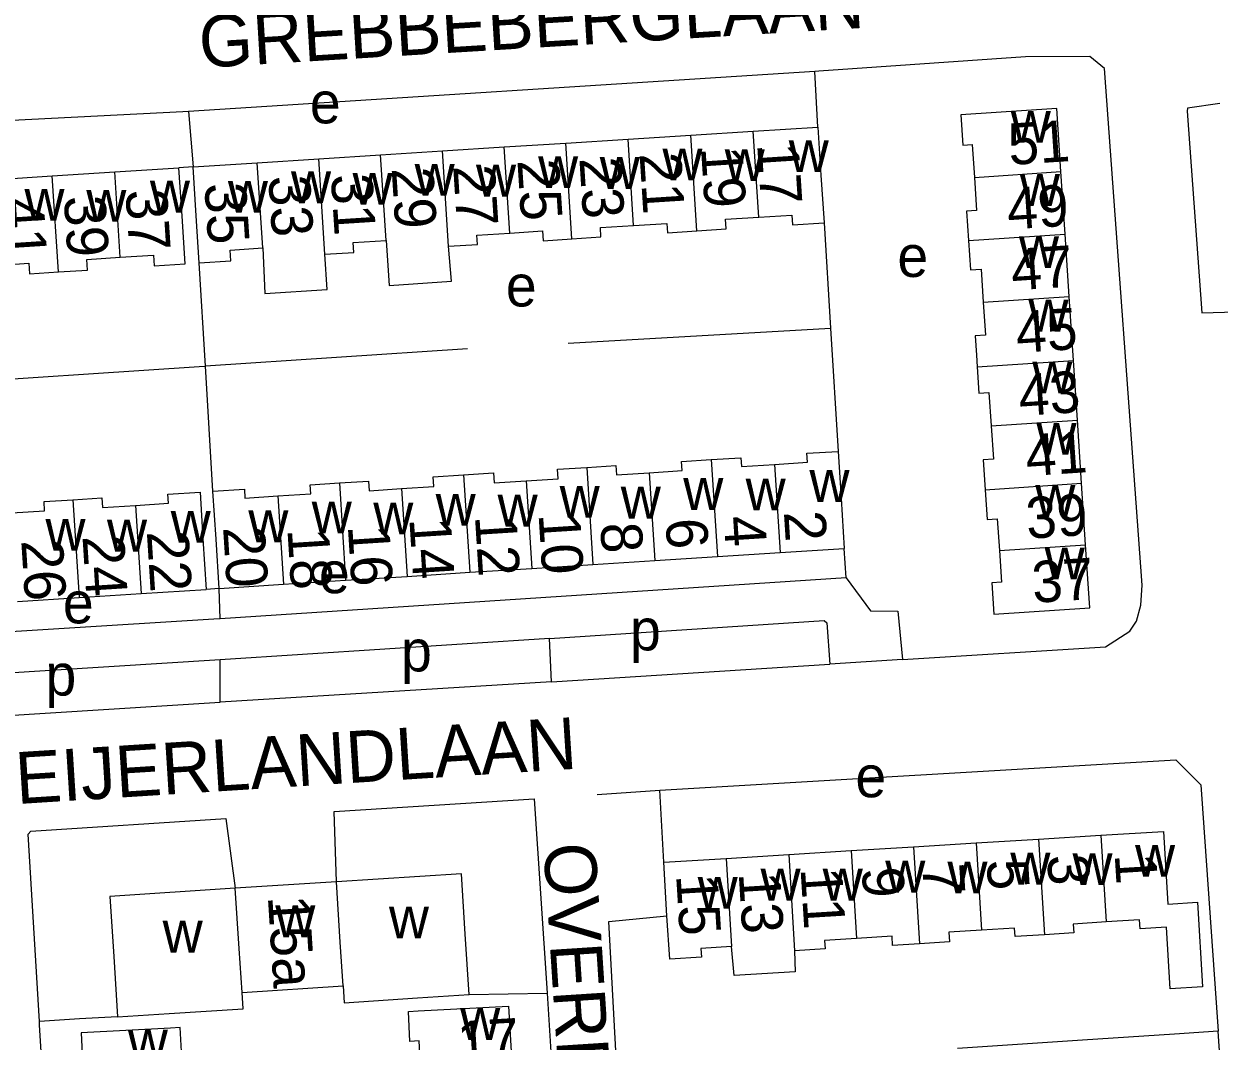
# Model space of a CAD drawing. Extents: x 159675 to 162108, y 386471 to 388472.
# Drawn here: x 160562.1 to 160677.4, y 387933.8 to 388032 of the extents above; entities that cross this region are included whole.
import ezdxf

# ---------------------------------------------------------------- set-up
doc = ezdxf.new("R2010")
doc.units = 0
for name, color, linetype in [('BLT_Basislijn', 7, 'Continuous'), ('BLT_Bebouwing', 7, 'Continuous'), ('BLT_Centroide', 7, 'Continuous'), ('BLT_Huisnummer', 7, 'Continuous'), ('BLT_Huisnummer_ tussenligend', 7, 'Continuous'), ('BLT_Onderverdeling_panden', 7, 'Continuous'), ('BLT_Straatnaam', 7, 'Continuous')]:
    doc.layers.add(name, color=color, linetype=linetype)

msp = doc.modelspace()

# ---------------------------------------------------------------- linework, layer by layer
at = {"layer": 'BLT_Basislijn'}
for p, q in [((160638.41, 388027.39), (160577.95, 388023.53)), ((160638.69, 388022.02), (160638.41, 388027.39)), ((160577.95, 388023.53), (160578.39, 388018.18)), ((160578.39, 388018.18), (160577.02, 388018.09)), ((160639.29, 388012.78), (160639.91, 388002.61)), ((160579.58, 387998.95), (160578.98, 388008.91)), ((160614.58, 388001.16), (160639.91, 388002.61)), ((160639.91, 388002.61), (160640.64, 387990.71)), ((160604.87, 388000.62), (160579.58, 387998.95)), ((160580.31, 387986.86), (160579.58, 387998.95)), ((160641.43, 387978.5), (160641.24, 387981.34)), ((160641.43, 387978.5), (160580.99, 387974.55)), ((160580.91, 387977.48), (160579.66, 387977.38)), ((160580.99, 387974.55), (160580.91, 387977.48)), ((160612.8, 387972.64), (160581, 387970.59)), ((160612.98, 387968.44), (160612.8, 387972.64)), ((160581, 387970.59), (160550.17, 387968.63)), ((160581, 387966.49), (160581, 387970.59)), ((160646.87, 387970.6), (160639.85, 387970.15)), ((160612.98, 387968.44), (160639.85, 387970.15)), ((160612.98, 387968.44), (160581, 387966.49)), ((160550.44, 387964.58), (160581, 387966.49)), ((160617.39, 387957.58), (160623.43, 387957.98)), ((160623.81, 387951.04), (160623.43, 387957.98)), ((160605.04, 387938.25), (160612.57, 387938.39)), ((160612.57, 387938.39), (160616.09, 387883.15))]:
    msp.add_line(p, q, dxfattribs=at)
for points in [[(160646.87, 387970.6), (160666.45, 387971.85), (160668.81, 387973.35), (160669.44, 387974.3), (160669.88, 387975.85), (160670, 387977.8), (160666.36, 388027.67), (160664.93, 388028.84), (160658.72, 388028.79), (160638.8, 388027.41), (160638.41, 388027.39)], [(160577.95, 388023.53), (160577.4, 388023.5), (160516.53, 388020.39)], [(160677.49, 388024.29), (160674.38, 388023.86), (160674.35, 388023.57), (160675.75, 388004.1), (160681.26, 388004.23)], [(160552.73, 387997.17), (160578.99, 387998.91), (160579.58, 387998.95)], [(160641.43, 387978.5), (160643.76, 387975.32), (160646.4, 387975.29), (160646.87, 387970.6)], [(160580.99, 387974.55), (160580.4, 387974.51), (160519.48, 387970.7)], [(160612.8, 387972.64), (160639.31, 387974.37), (160639.56, 387974.15), (160639.85, 387970.15)], [(160623.43, 387957.98), (160673.26, 387960.91), (160675.65, 387958.52), (160677.32, 387934.73)], [(160592.22, 387949.14), (160592.02, 387955.94), (160611.31, 387957.17), (160612.57, 387938.39)], [(160563.56, 387935.67), (160562.48, 387953.76), (160562.74, 387954.03), (160581.55, 387955.26), (160582.46, 387948.52)], [(160626.68, 387931.37), (160619.29, 387931.07), (160618.52, 387945.33), (160624.13, 387945.86)], [(160571.1, 387936.12), (160567.42, 387935.91), (160563.56, 387935.67)], [(160567.08, 387879.85), (160563.58, 387935.29), (160563.56, 387935.67)], [(160677.32, 387934.73), (160673.1, 387934.42), (160664.24, 387933.86), (160652.18, 387933.04)], [(160673.63, 387866.07), (160679.58, 387866.28), (160681.79, 387868.46), (160677.32, 387934.73)]]:
    msp.add_lwpolyline(points, dxfattribs=at)
at = {"layer": 'BLT_Bebouwing'}
for p, q in [((160620.37, 388020.86), (160626.42, 388021.24)), ((160626.42, 388021.24), (160632.46, 388021.62)), ((160632.46, 388021.62), (160638.69, 388022.02)), ((160602.46, 388019.72), (160608.41, 388020.1)), ((160608.41, 388020.1), (160614.37, 388020.47)), ((160614.37, 388020.47), (160620.37, 388020.86)), ((160584.58, 388018.58), (160590.53, 388018.96)), ((160590.53, 388018.96), (160596.49, 388019.34)), ((160596.49, 388019.34), (160602.46, 388019.72)), ((160564.8, 388017.31), (160570.82, 388017.69)), ((160570.82, 388017.69), (160577.02, 388018.09)), ((160578.39, 388018.18), (160584.58, 388018.58)), ((160662.56, 388011.69), (160662.16, 388017.72)), ((160558.83, 388016.92), (160564.8, 388017.31)), ((160662.96, 388005.67), (160662.56, 388011.69)), ((160663.37, 387999.49), (160662.96, 388005.67)), ((160654, 388000), (160654.07, 387998.87)), ((160663.75, 387993.72), (160663.37, 387999.49)), ((160664.15, 387987.63), (160663.75, 387993.72)), ((160664.54, 387981.69), (160664.15, 387987.63)), ((160629, 387980.55), (160635.05, 387980.94)), ((160635.05, 387980.94), (160641.24, 387981.34)), ((160664.95, 387975.61), (160664.54, 387981.69)), ((160611.08, 387979.41), (160616.98, 387979.79)), ((160616.98, 387979.79), (160622.96, 387980.17)), ((160622.96, 387980.17), (160629, 387980.55)), ((160593.11, 387978.26), (160599.05, 387978.64)), ((160599.05, 387978.64), (160605.09, 387979.03)), ((160605.09, 387979.03), (160611.08, 387979.41)), ((160573.37, 387976.98), (160579.66, 387977.38)), ((160580.91, 387977.48), (160587.12, 387977.88)), ((160587.12, 387977.88), (160593.11, 387978.26)), ((160561.44, 387976.21), (160567.39, 387976.59)), ((160567.39, 387976.59), (160573.37, 387976.98)), ((160653.96, 387952.9), (160659.99, 387953.27)), ((160659.99, 387953.27), (160666.02, 387953.65)), ((160629.85, 387951.41), (160635.88, 387951.78)), ((160635.88, 387951.78), (160641.9, 387952.16)), ((160641.9, 387952.16), (160647.93, 387952.53)), ((160647.93, 387952.53), (160653.96, 387952.9)), ((160623.81, 387951.04), (160629.85, 387951.41)), ((160624.13, 387945.86), (160623.81, 387951.04)), ((160592.22, 387949.14), (160582.46, 387948.52)), ((160605.04, 387938.25), (160604.66, 387944.1)), ((160570.73, 387941.93), (160571.1, 387936.12)), ((160583.11, 387938.47), (160592.86, 387939.09))]:
    msp.add_line(p, q, dxfattribs=at)
for points in [[(160662.16, 388017.72), (160661.75, 388023.83), (160652.48, 388023.21), (160652.67, 388020.29), (160653.6, 388020.35), (160653.81, 388017.16)], [(160638.69, 388022.02), (160638.99, 388017.38), (160639.29, 388012.78)], [(160571.35, 388009.45), (160574.56, 388009.65), (160574.62, 388008.62), (160577.62, 388008.81), (160577.32, 388013.42), (160577.02, 388018.09)], [(160578.98, 388008.91), (160578.69, 388013.46), (160578.39, 388018.18)], [(160653.81, 388017.16), (160654.02, 388013.98), (160653.05, 388013.91), (160653.24, 388011.08)], [(160627.01, 388012), (160629.84, 388012.18), (160629.78, 388013.12), (160632.99, 388013.32)], [(160632.99, 388013.32), (160636.19, 388013.53), (160636.26, 388012.59), (160639.29, 388012.78)], [(160603.05, 388010.51), (160605.85, 388010.69), (160605.79, 388011.59), (160608.95, 388011.79)], [(160608.95, 388011.79), (160612.11, 388011.99), (160612.17, 388011.05), (160614.96, 388011.23)], [(160614.96, 388011.23), (160617.76, 388011.41), (160617.71, 388012.31), (160620.91, 388012.52)], [(160620.91, 388012.52), (160624.12, 388012.72), (160624.17, 388011.82), (160627.01, 388012)], [(160591.12, 388009.74), (160593.92, 388009.92), (160593.85, 388010.88), (160597.02, 388011.08)], [(160597.02, 388011.08), (160597.32, 388006.74), (160603.34, 388007.13), (160603.05, 388010.51)], [(160653.24, 388011.08), (160653.43, 388008.24), (160654.45, 388008.31), (160654.66, 388005.11)], [(160565.4, 388008.03), (160568.21, 388008.21), (160568.14, 388009.24), (160571.35, 388009.45)], [(160578.98, 388008.91), (160582.03, 388009.1), (160581.96, 388010.15), (160585.11, 388010.35)], [(160585.11, 388010.35), (160585.32, 388005.95), (160591.33, 388006.33), (160591.12, 388009.74)], [(160559.36, 388008.66), (160562.53, 388008.87), (160562.59, 388007.85), (160565.4, 388008.03)], [(160654.66, 388005.11), (160654.87, 388001.92), (160653.87, 388001.86), (160654, 388000)], [(160654.07, 387998.87), (160654.24, 387996.32), (160655.21, 387996.38), (160655.42, 387993.17)], [(160655.42, 387993.17), (160655.63, 387989.95), (160654.64, 387989.89), (160654.83, 387987.01)], [(160622.42, 387988.65), (160625.59, 387988.85), (160625.53, 387989.74), (160628.4, 387989.92)], [(160628.4, 387989.92), (160631.26, 387990.1), (160631.32, 387989.24), (160634.51, 387989.45)], [(160634.51, 387989.45), (160637.69, 387989.65), (160637.64, 387990.52), (160640.64, 387990.71)], [(160640.64, 387990.71), (160640.93, 387986.15), (160641.24, 387981.34)], [(160610.54, 387987.87), (160613.62, 387988.07), (160613.56, 387988.98), (160616.38, 387989.16)], [(160616.38, 387989.16), (160619.2, 387989.34), (160619.25, 387988.44), (160622.42, 387988.65)], [(160586.57, 387986.4), (160589.76, 387986.6), (160589.7, 387987.48), (160592.51, 387987.66)], [(160592.51, 387987.66), (160595.33, 387987.84), (160595.39, 387986.91), (160598.51, 387987.11)], [(160598.51, 387987.11), (160601.63, 387987.31), (160601.57, 387988.25), (160604.49, 387988.43)], [(160604.49, 387988.43), (160607.4, 387988.62), (160607.46, 387987.68), (160610.54, 387987.87)], [(160572.83, 387985.49), (160576.02, 387985.7), (160575.96, 387986.58), (160579.06, 387986.77), (160579.34, 387982.26), (160579.66, 387977.38)], [(160580.31, 387986.86), (160583.34, 387987.05), (160583.39, 387986.2), (160586.57, 387986.4)], [(160580.91, 387977.48), (160580.61, 387982.24), (160580.31, 387986.86)], [(160654.83, 387987.01), (160655.02, 387984.13), (160656.01, 387984.2), (160656.21, 387981.13)], [(160560.89, 387984.77), (160564.06, 387984.97), (160564, 387985.86), (160566.79, 387986.03)], [(160566.79, 387986.03), (160569.58, 387986.21), (160569.64, 387985.29), (160572.83, 387985.49)], [(160656.21, 387981.13), (160656.42, 387978.07), (160655.48, 387978.01), (160655.68, 387974.99), (160664.95, 387975.61)], [(160666.02, 387953.65), (160672.04, 387954.02), (160672.48, 387947), (160675.33, 387947.18), (160675.83, 387939), (160672.71, 387938.81), (160672.35, 387944.77), (160669.8, 387944.61), (160669.74, 387945.47), (160666.53, 387945.27)], [(160604.66, 387944.1), (160604.29, 387949.91), (160592.22, 387949.14)], [(160582.46, 387948.52), (160570.35, 387947.74), (160570.73, 387941.93)], [(160630.37, 387942.91), (160627.41, 387942.72), (160627.46, 387941.87), (160624.39, 387941.68), (160624.13, 387945.86)], [(160666.53, 387945.27), (160663.34, 387945.07), (160663.39, 387944.21), (160660.56, 387944.04)], [(160648.51, 387943.16), (160645.9, 387943), (160645.85, 387943.89), (160642.43, 387943.68)], [(160654.48, 387944.49), (160651.34, 387944.29), (160651.4, 387943.34), (160648.51, 387943.16)], [(160660.56, 387944.04), (160657.73, 387943.86), (160657.68, 387944.68), (160654.48, 387944.49)], [(160636.45, 387942.48), (160636.5, 387940.47), (160630.62, 387940.11), (160630.37, 387942.91)], [(160642.43, 387943.68), (160639.34, 387943.49), (160639.39, 387942.66), (160636.45, 387942.48)], [(160592.86, 387939.09), (160592.96, 387937.47), (160600.06, 387937.93), (160605.04, 387938.25)], [(160571.1, 387936.12), (160576.09, 387936.44), (160583.21, 387936.89), (160583.11, 387938.47)], [(160600.38, 387930.6), (160600.21, 387933.79), (160599.32, 387933.74), (160599.17, 387936.63), (160600.12, 387936.68), (160608.84, 387937.15), (160609.2, 387931.13)], [(160576.62, 387928.97), (160576.45, 387932.15), (160577.29, 387932.19), (160577.13, 387935.08), (160576.2, 387935.03), (160567.6, 387934.57), (160567.86, 387928.53)]]:
    msp.add_lwpolyline(points, dxfattribs=at)
at = {"layer": 'BLT_Onderverdeling_panden'}
for p, q in [((160627.01, 388012), (160626.42, 388021.24)), ((160632.99, 388013.32), (160632.46, 388021.62)), ((160608.95, 388011.79), (160608.41, 388020.1)), ((160614.96, 388011.23), (160614.37, 388020.47)), ((160620.91, 388012.52), (160620.37, 388020.86)), ((160591.12, 388009.74), (160590.53, 388018.96)), ((160597.02, 388011.08), (160596.49, 388019.34)), ((160603.05, 388010.51), (160602.46, 388019.72)), ((160571.35, 388009.45), (160570.82, 388017.69)), ((160585.11, 388010.35), (160584.58, 388018.58)), ((160653.81, 388017.16), (160662.16, 388017.72)), ((160565.4, 388008.03), (160564.8, 388017.31)), ((160653.24, 388011.08), (160662.56, 388011.69)), ((160654.66, 388005.11), (160662.96, 388005.67)), ((160654.07, 387998.87), (160663.37, 387999.49)), ((160655.42, 387993.17), (160663.75, 387993.72)), ((160628.4, 387989.92), (160629, 387980.55)), ((160616.38, 387989.16), (160616.98, 387979.79)), ((160634.51, 387989.45), (160635.05, 387980.94)), ((160592.51, 387987.66), (160593.11, 387978.26)), ((160604.49, 387988.43), (160605.09, 387979.03)), ((160610.54, 387987.87), (160611.08, 387979.41)), ((160622.42, 387988.65), (160622.96, 387980.17)), ((160654.83, 387987.01), (160664.15, 387987.63)), ((160586.57, 387986.4), (160587.12, 387977.88)), ((160598.51, 387987.11), (160599.05, 387978.64)), ((160566.79, 387986.03), (160567.39, 387976.59)), ((160572.83, 387985.49), (160573.37, 387976.98)), ((160656.21, 387981.13), (160664.54, 387981.69)), ((160659.99, 387953.27), (160660.56, 387944.04)), ((160666.02, 387953.65), (160666.53, 387945.27)), ((160635.88, 387951.78), (160636.45, 387942.48)), ((160641.9, 387952.16), (160642.43, 387943.68)), ((160647.93, 387952.53), (160648.51, 387943.16)), ((160653.96, 387952.9), (160654.48, 387944.49)), ((160629.85, 387951.41), (160630.37, 387942.91)), ((160582.83, 387942.71), (160582.46, 387948.52)), ((160592.59, 387943.33), (160592.22, 387949.14)), ((160583.11, 387938.47), (160582.83, 387942.71)), ((160592.86, 387939.09), (160592.59, 387943.33))]:
    msp.add_line(p, q, dxfattribs=at)

# ---------------------------------------------------------------- texts
at = {"layer": 'BLT_Centroide'}
for s, p in [('e', (160589.66, 388022.38)), ('w', (160657.31, 388020.5)), ('w', (160623.69, 388016.88)), ('w', (160629.7, 388016.81)), ('w', (160635.88, 388017.67)), ('w', (160611.69, 388016.14)), ('w', (160617.64, 388016.05)), ('w', (160587.84, 388014.66)), ('w', (160593.78, 388014.53)), ('w', (160599.77, 388015.39)), ('w', (160605.7, 388015.31)), ('w', (160574.22, 388013.77)), ('w', (160581.75, 388013.75)), ('w', (160658.19, 388014.41)), ('w', (160562.11, 388012.98)), ('w', (160568.08, 388012.88)), ('e', (160646.37, 388007.55)), ('w', (160658.1, 388008.41)), ('e', (160608.58, 388004.7)), ('w', (160659.02, 388002.28)), ('w', (160659.39, 387996.31)), ('w', (160659.79, 387990.38)), ('w', (160637.88, 387985.83)), ('w', (160625.7, 387985.05)), ('w', (160631.72, 387985)), ('w', (160601.8, 387983.53)), ('w', (160607.78, 387983.44)), ('w', (160613.77, 387984.3)), ('w', (160619.67, 387984.22)), ('w', (160659.68, 387984.38)), ('w', (160589.84, 387982.78)), ('w', (160595.78, 387982.69)), ('w', (160564.14, 387981.12)), ('w', (160570.08, 387981.03)), ('w', (160576.23, 387981.88)), ('w', (160583.72, 387981.94)), ('w', (160660.59, 387978.34)), ('e', (160590.54, 387977.01)), ('e', (160565.82, 387974.1)), ('p', (160620.56, 387971.49)), ('p', (160598.46, 387969.46)), ('p', (160564.14, 387967.13)), ('e', (160642.32, 387957.31)), ('w', (160657.27, 387948.88)), ('w', (160663.27, 387948.84)), ('w', (160669.31, 387949.64)), ('w', (160645.2, 387948.11)), ('w', (160651.2, 387948.02)), ('w', (160627.09, 387946.55)), ('w', (160633.16, 387947.34)), ('w', (160639.16, 387947.33)), ('w', (160586.32, 387943.8)), ('w', (160597.29, 387943.69)), ('w', (160575.45, 387942.31)), ('w', (160604.17, 387933.88)), ('w', (160572.09, 387931.81))]:
    msp.add_text(s, height=4, dxfattribs=at).set_placement(p)
at = {"layer": 'BLT_Huisnummer'}
for s, rotation, p in [('51', 3.7896, (160657.18, 388018.35)), ('17', 273.6655, (160632.83, 388020.37)), ('25', 273.6678, (160609.69, 388018.81)), ('21', 273.6693, (160621.48, 388019.45)), ('29', 273.6684, (160597.55, 388018.03)), ('33', 273.6713, (160585.65, 388017.25)), ('37', 273.6662, (160571.86, 388015.9)), ('41', 273.6738, (160559.95, 388015.09)), ('45', 3.7862, (160657.92, 388000.21)), ('41', 3.7986, (160658.86, 387988.31)), ('10', 273.6538, (160611.73, 387984.65)), ('6', 273.6745, (160623.98, 387984.14)), ('2', 273.6662, (160635.41, 387984.86)), ('14', 273.6588, (160599.26, 387984.21)), ('26', 273.6665, (160561.8, 387982.1)), ('22', 273.6634, (160573.92, 387982.96)), ('18', 273.6641, (160587.49, 387983.19)), ('37', 3.7972, (160659.48, 387976.07)), ('5', 273.5356, (160654.98, 387951.22)), ('1', 273.538, (160667.34, 387951.79)), ('15', 273.5276, (160625.01, 387949.79)), ('9', 273.5342, (160642.93, 387950.47)), ('15a', 273.6629, (160585.6, 387947.73)), ('17', 3.4494, (160604.01, 387931.66))]:
    msp.add_text(s, height=4, rotation=rotation, dxfattribs=at).set_placement(p)
at = {"layer": 'BLT_Huisnummer_ tussenligend'}
for s, rotation, p in [('23', 273.6708, (160615.67, 388019.01)), ('19', 273.6781, (160627.41, 388020.04)), ('27', 273.6662, (160603.49, 388018.26)), ('35', 273.6711, (160579.48, 388016.54)), ('31', 273.6777, (160591.68, 388017.4)), ('49', 3.8063, (160657.07, 388012.12)), ('39', 273.6713, (160565.91, 388015.3)), ('47', 3.7862, (160657.46, 388006.24)), ('43', 3.7986, (160658.19, 387994.12)), ('39', 3.7972, (160658.9, 387982.26)), ('12', 273.6538, (160605.59, 387984.46)), ('4', 273.6584, (160629.6, 387984.38)), ('20', 273.6752, (160581.28, 387983.37)), ('16', 273.6588, (160593.32, 387983.51)), ('8', 273.6572, (160617.68, 387983.74)), ('24', 273.6634, (160567.71, 387982.51)), ('7', 273.538, (160648.76, 387950.79)), ('3', 273.5361, (160660.82, 387951.68)), ('13', 273.5276, (160631.05, 387949.98)), ('11', 273.5373, (160637.02, 387950.42))]:
    msp.add_text(s, height=4, rotation=rotation, dxfattribs=at).set_placement(p)
at = {"layer": 'BLT_Straatnaam'}
for s, rotation, p in [('GREBBEBERGLAAN', 3.4589, (160579.1, 388027.73)), ('BEIJERLANDLAAN', 3.6128, (160556.94, 387956.37)), ('OVERFLAKKEESTRAAT', 273.7155, (160612.2, 387952.76))]:
    msp.add_text(s, height=5, rotation=rotation, dxfattribs=at).set_placement(p)

doc.saveas('drawing.dxf')
